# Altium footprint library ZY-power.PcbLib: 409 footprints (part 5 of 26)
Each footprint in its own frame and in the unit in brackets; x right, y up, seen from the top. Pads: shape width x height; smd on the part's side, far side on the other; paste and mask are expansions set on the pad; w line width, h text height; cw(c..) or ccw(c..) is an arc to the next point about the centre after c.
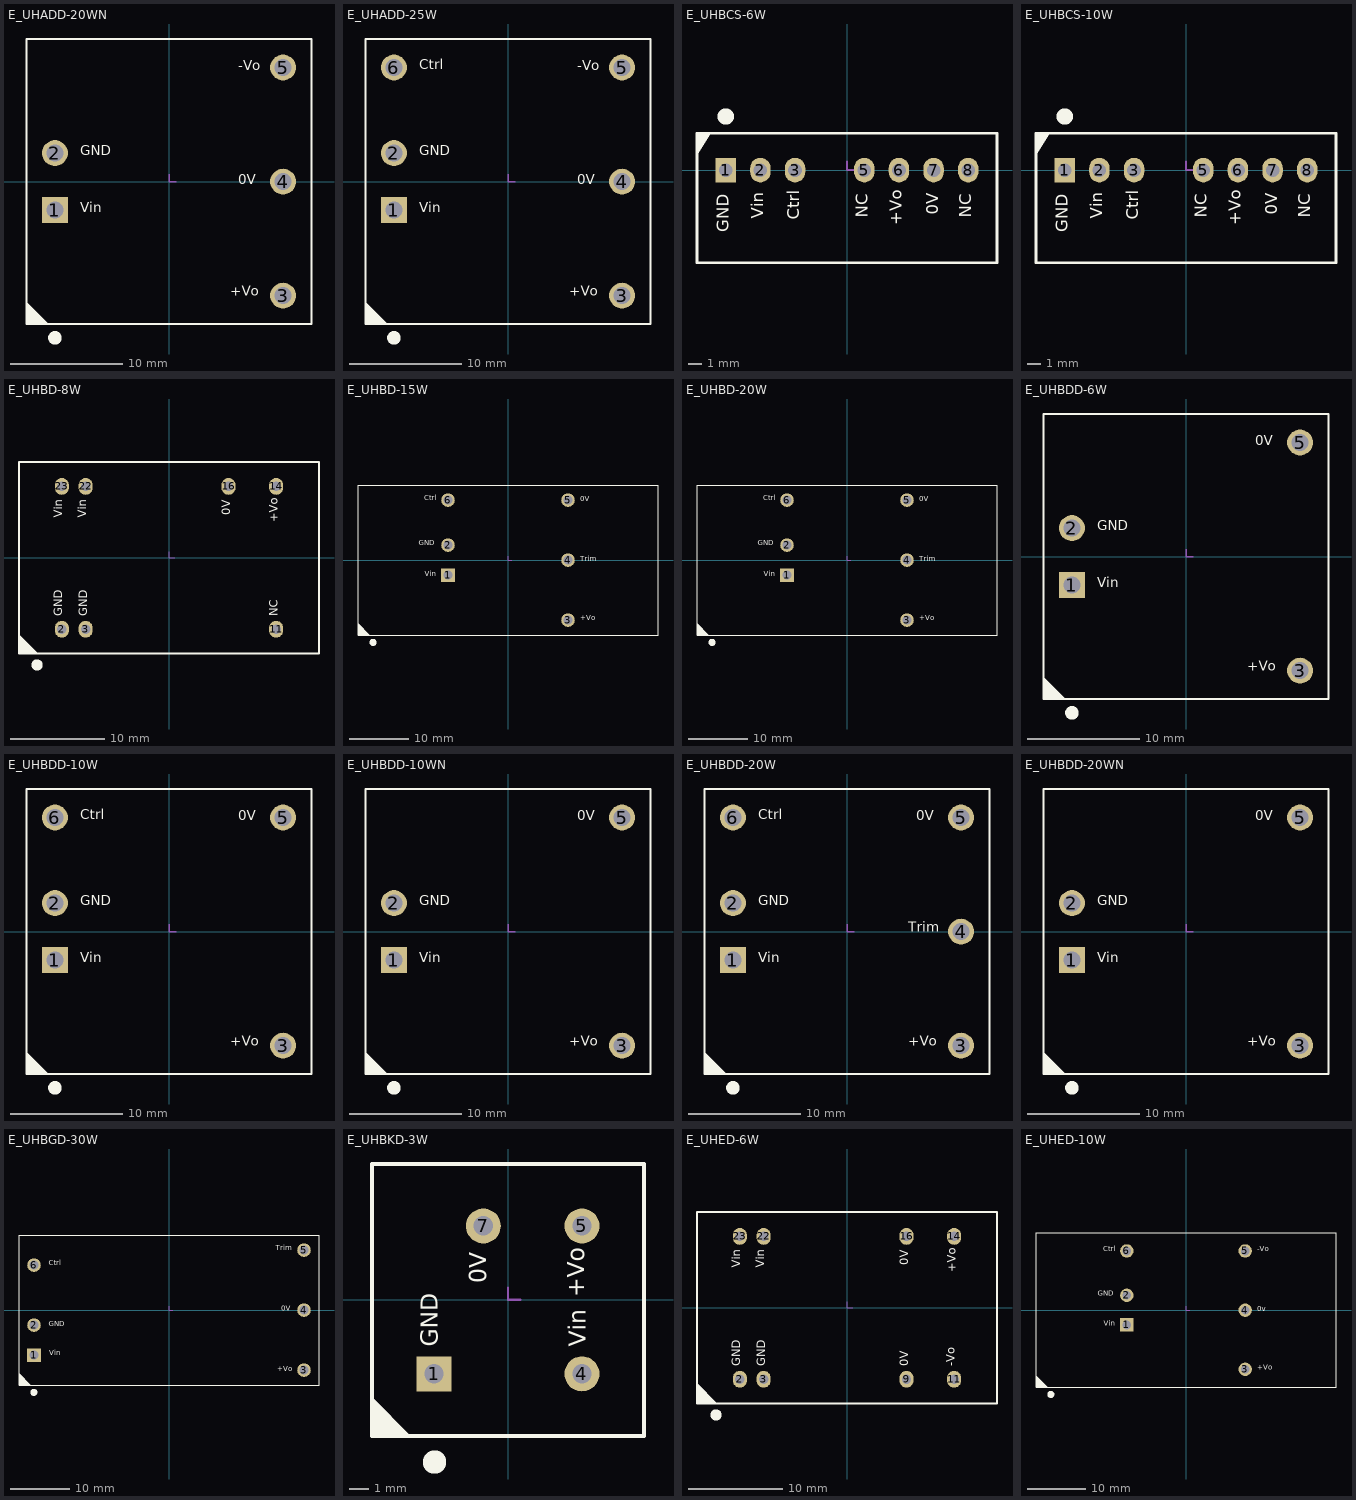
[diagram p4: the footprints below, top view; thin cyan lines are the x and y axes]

## E_UHADD-20WN [mm]
height 11.7
pads (5):
  rect 2.3x2.3 hole 1.5: 1(-10.16,-2.54)
  round 2.3 hole 1.5: 2(-10.16,2.54) 3(10.16,-10.16) 4(10.16,0) 5(10.16,10.16)
Top Overlay:
  circle w1: c-10.16,-13.925 r0.1
  region: -12.7,-12.7 -10.725,-12.7 -12.7,-10.725
  lines w0.2: -12.7,-12.7 12.7,-12.7 12.7,12.7 -12.7,12.7 -12.7,-12.7
  text "-Vo" at 6.175,9.625 h1.52
  text "+Vo" at 5.435,-10.5 h1.52
  text "Vin" at -7.9,-3.025 h1.52
  text "GND" at -7.901,2.05 h1.52
  text "0V" at 6.175,-0.535 h1.52
Mechanical 15:
  lines w0.127: 0,0.635 0,0 0.635,0
3D body: height -1.1, standoff -6.01, extent 9.664,-0.499 10.66,0.499
3D body: height 11.8, standoff 0, extent -12.7,-12.7 12.7,12.7
3D body: height -1.1, standoff -6.01, extent -10.656,2.041 -9.66,3.039
3D body: height -1.1, standoff -6.01, extent -10.656,-3.039 -9.66,-2.041
3D body: height -1.1, standoff -6.01, extent 9.664,-10.659 10.66,-9.661
3D body: height -1.1, standoff -6.01, extent 9.664,9.661 10.66,10.659

## E_UHADD-25W [mm]
height 11.8
pads (6):
  rect 2.3x2.3 hole 1.5: 1(-10.16,-2.54)
  round 2.3 hole 1.5: 2(-10.16,2.54) 3(10.16,-10.16) 4(10.16,0) 5(10.16,10.16) 6(-10.16,10.16)
Top Overlay:
  circle w1: c-10.16,-13.925 r0.1
  region: -12.7,-12.7 -10.725,-12.7 -12.7,-10.725
  lines w0.2: -12.7,-12.7 -12.7,12.7 12.7,12.7 12.7,-12.7 -12.7,-12.7
  text "0V" at 6.175,-0.535 h1.52
  text "GND" at -7.901,2.05 h1.52
  text "Vin" at -7.9,-3.025 h1.52
  text "Ctrl" at -7.901,9.7 h1.52
  text "+Vo" at 5.435,-10.5 h1.52
  text "-Vo" at 6.175,9.625 h1.52
Mechanical 15:
  lines w0.127: 0,0.635 0,0 0.635,0
3D body: height 11.8, standoff 0, extent -12.7,-12.7 12.7,12.7
3D body: height -1.1, standoff -6.01, extent -10.656,2.041 -9.66,3.039
3D body: height -1.1, standoff -6.01, extent -10.656,-3.039 -9.66,-2.041
3D body: height -1.1, standoff -6.01, extent 9.664,-10.659 10.66,-9.661
3D body: height -1.1, standoff -6.01, extent 9.664,9.661 10.66,10.659
3D body: height -1.1, standoff -6.01, extent -10.656,9.661 -9.66,10.659
3D body: height -1.1, standoff -6.01, extent 9.664,-0.499 10.66,0.499

## E_UHBCS-6W [mm]
height 12
pads (7):
  rect 1.5x1.8 hole 1: 1(-8.89,0)
  oval 1.5x1.8 hole 1: 2(-6.35,0) 3(-3.81,0) 5(1.27,0) 6(3.81,0) 7(6.35,0) 8(8.89,0)
Top Overlay:
  circle w1: c-8.89,3.925 r0.1
  region: -11,1.114 -11,2.7 -10.006,2.7
  lines w0.2: -11,-6.8 11,-6.8 11,2.7 -11,2.7 -11,-6.8
  text "NC" at 1.803,-3.502 h1.52
  text "Ctrl" at -3.226,-3.648 h1.52
  text "GND" at -8.382,-4.573 h1.52
  text "Vin" at -5.842,-3.563 h1.52
  text "+Vo" at 4.318,-4.031 h1.52
  text "0V" at 6.985,-3.291 h1.52
  text "NC" at 9.398,-3.502 h1.52
Mechanical 15:
  lines w0.127: 0,0.635 0,0 0.635,0
3D body: height 12, standoff 0, extent -10.93,-6.8 11,2.7
3D body "zhenjao01.stp": height 8.36, standoff -4.08, extent -9.59,-0.12 -8.19,1.48
3D body "zhenjao01.stp": height 8.36, standoff -4.08, extent -7.05,-0.12 -5.65,1.48
3D body "zhenjao01.stp": height 8.36, standoff -4.08, extent -4.51,-0.12 -3.11,1.48
3D body "zhenjao01.stp": height 8.36, standoff -4.08, extent 0.57,-0.12 1.97,1.48
3D body "zhenjao01.stp": height 8.36, standoff -4.08, extent 3.11,-0.12 4.51,1.48
3D body "zhenjao01.stp": height 8.36, standoff -4.08, extent 5.65,-0.12 7.05,1.48
3D body "zhenjao01.stp": height 8.36, standoff -4.08, extent 8.19,-0.12 9.59,1.48

## E_UHBCS-10W [mm]
height 12
pads (7):
  rect 1.5x1.8 hole 1: 1(-8.89,0)
  oval 1.5x1.8 hole 1: 2(-6.35,0) 3(-3.81,0) 5(1.27,0) 6(3.81,0) 7(6.35,0) 8(8.89,0)
Top Overlay:
  circle w1: c-8.89,3.925 r0.1
  region: -11,1.114 -11,2.7 -10.006,2.7
  lines w0.2: -11,-6.8 -11,2.7 11,2.7 11,-6.8 -11,-6.8
  text "NC" at 9.398,-3.502 h1.52
  text "0V" at 6.985,-3.291 h1.52
  text "+Vo" at 4.318,-4.031 h1.52
  text "Vin" at -5.842,-3.563 h1.52
  text "GND" at -8.382,-4.573 h1.52
  text "Ctrl" at -3.226,-3.648 h1.52
  text "NC" at 1.803,-3.502 h1.52
Mechanical 15:
  lines w0.127: 0,0.635 0,0 0.635,0
3D body "zhenjao01.stp": height 8.36, standoff -4.08, extent 8.19,-0.12 9.59,1.48
3D body "zhenjao01.stp": height 8.36, standoff -4.08, extent 5.65,-0.12 7.05,1.48
3D body "zhenjao01.stp": height 8.36, standoff -4.08, extent 3.11,-0.12 4.51,1.48
3D body "zhenjao01.stp": height 8.36, standoff -4.08, extent 0.57,-0.12 1.97,1.48
3D body "zhenjao01.stp": height 8.36, standoff -4.08, extent -4.51,-0.12 -3.11,1.48
3D body "zhenjao01.stp": height 8.36, standoff -4.08, extent -7.05,-0.12 -5.65,1.48
3D body "zhenjao01.stp": height 8.36, standoff -4.08, extent -9.59,-0.12 -8.19,1.48
3D body: height 12, standoff 0, extent -10.93,-6.8 11,2.7

## E_UHBD-8W [mm]
height 11
pads (7):
  oval 1.5x1.8 hole 1: 2(-11.43,-7.62) 3(-8.89,-7.62) 11(11.43,-7.62) 14(11.43,7.62) 16(6.35,7.62) 22(-8.89,7.62) 23(-11.43,7.62)
Top Overlay:
  circle w1: c-14.072,-11.425 r0.1
  region: -16,-10.2 -14.025,-10.2 -16,-8.225
  lines w0.2: -16,-10.2 -16,10.2 16,10.2 16,-10.2 -16,-10.2
  text "GND" at -11.049,-6.223 h1.52
  text "GND" at -8.382,-6.223 h1.52
  text "Vin" at -11.049,4.278 h1.52
  text "Vin" at -8.509,4.278 h1.52
  text "NC" at 11.938,-6.223 h1.52
  text "+Vo" at 11.938,3.81 h1.52
  text "0V" at 6.858,4.55 h1.52
Mechanical 15:
  lines w0.127: 0,0.635 0,0 0.635,0
3D body "zhen01.stp": height 6.09, standoff -4.41, extent -9.14,-7.87 -8.64,-7.37
3D body "zhen01.stp": height 6.09, standoff -4.41, extent -11.68,-7.87 -11.18,-7.37
3D body "zhen01.stp": height 6.09, standoff -4.41, extent 11.18,-7.87 11.68,-7.37
3D body "zhen01.stp": height 6.09, standoff -4.41, extent 11.18,7.37 11.68,7.87
3D body "zhen01.stp": height 6.09, standoff -4.41, extent 6.1,7.37 6.6,7.87
3D body "zhen01.stp": height 6.09, standoff -4.41, extent -9.14,7.37 -8.64,7.87
3D body "zhen01.stp": height 6.09, standoff -4.41, extent -11.68,7.37 -11.18,7.87
3D body: height 11, standoff 0, extent -16,-10.2 16,10.2

## E_UHBD-15W [mm]
height 12.7
pads (6):
  rect 2.3x2.3 hole 1.5: 1(-10.16,-2.54)
  round 2.3 hole 1.5: 2(-10.16,2.54) 3(10.16,-10.16) 4(10.16,0) 5(10.16,10.16) 6(-10.16,10.16)
Top Overlay:
  circle w1: c-22.86,-13.925 r0.1
  region: -25.4,-12.7 -23.425,-12.7 -25.4,-10.725
  lines w0.2: -25.4,-12.7 -25.4,12.7 25.4,12.7 25.4,-12.7 -25.4,-12.7
  text "+Vo" at 12.192,-10.541 h1.52
  text "0V" at 12.192,9.652 h1.52
  text "GND" at -15.113,2.159 h1.52
  text "Vin" at -14.103,-3.048 h1.52
  text "Trim" at 12.192,-0.508 h1.52
  text "Ctrl" at -14.187,9.779 h1.52
Mechanical 15:
  lines w0.127: 0,0.635 0,0 0.635,0
3D body: height 12, standoff 0, extent -25.4,-12.7 25.4,12.7
3D body: height -1.1, standoff -6.01, extent -10.656,2.041 -9.66,3.039
3D body: height -1.1, standoff -6.01, extent -10.656,-3.039 -9.66,-2.041
3D body: height -1.1, standoff -6.01, extent -10.656,9.661 -9.66,10.659
3D body: height -1.1, standoff -6.01, extent 9.664,9.661 10.66,10.659
3D body: height -1.1, standoff -6.01, extent 9.664,-10.659 10.66,-9.661
3D body: height -1.1, standoff -6.01, extent 9.664,-0.499 10.66,0.499

## E_UHBD-20W [mm]
pads (6):
  rect 2.3x2.3 hole 1.5: 1(-10.16,-2.54)
  round 2.3 hole 1.5: 2(-10.16,2.54) 3(10.16,-10.16) 4(10.16,0) 5(10.16,10.16) 6(-10.16,10.16)
Top Overlay:
  circle w1: c-22.86,-13.925 r0.1
  region: -25.4,-12.7 -23.425,-12.7 -25.4,-10.725
  lines w0.2: -25.4,-12.7 -25.4,12.7 25.4,12.7 25.4,-12.7 -25.4,-12.7
  text "Ctrl" at -14.187,9.779 h1.52
  text "Trim" at 12.192,-0.508 h1.52
  text "Vin" at -14.103,-3.048 h1.52
  text "GND" at -15.113,2.159 h1.52
  text "0V" at 12.192,9.652 h1.52
  text "+Vo" at 12.192,-10.541 h1.52
Mechanical 15:
  lines w0.127: 0,0.635 0,0 0.635,0
3D body: height 12, standoff 0, extent -25.4,-12.7 25.4,12.7
3D body: height -1.1, standoff -6.01, extent -10.656,2.041 -9.66,3.039
3D body: height -1.1, standoff -6.01, extent -10.656,-3.039 -9.66,-2.041
3D body: height -1.1, standoff -6.01, extent -10.656,9.661 -9.66,10.659
3D body: height -1.1, standoff -6.01, extent 9.664,9.661 10.66,10.659
3D body: height -1.1, standoff -6.01, extent 9.664,-10.659 10.66,-9.661
3D body: height -1.1, standoff -6.01, extent 9.664,-0.499 10.66,0.499

## E_UHBDD-6W [mm]
height 11.7
pads (4):
  rect 2.3x2.3 hole 1.5: 1(-10.16,-2.54)
  round 2.3 hole 1.5: 2(-10.16,2.54) 3(10.16,-10.16) 5(10.16,10.16)
Top Overlay:
  circle w1: c-10.16,-13.925 r0.1
  region: -12.7,-12.7 -10.725,-12.7 -12.7,-10.725
  lines w0.2: -12.7,-12.7 12.7,-12.7 12.7,12.7 -12.7,12.7 -12.7,-12.7
  text "0V" at 6.175,9.625 h1.52
  text "+Vo" at 5.435,-10.5 h1.52
  text "Vin" at -7.9,-3.025 h1.52
  text "GND" at -7.901,2.05 h1.52
Mechanical 15:
  lines w0.127: 0,0.635 0,0 0.635,0
3D body: height -1.1, standoff -6.01, extent 9.664,9.661 10.66,10.659
3D body: height -1.1, standoff -6.01, extent 9.664,-10.659 10.66,-9.661
3D body: height -1.1, standoff -6.01, extent -10.656,-3.039 -9.66,-2.041
3D body: height -1.1, standoff -6.01, extent -10.656,2.041 -9.66,3.039
3D body: height 11.8, standoff 0, extent -12.7,-12.7 12.7,12.7

## E_UHBDD-10W [mm]
height 11.8
pads (5):
  rect 2.3x2.3 hole 1.5: 1(-10.16,-2.54)
  round 2.3 hole 1.5: 2(-10.16,2.54) 3(10.16,-10.16) 5(10.16,10.16) 6(-10.16,10.16)
Top Overlay:
  circle w1: c-10.16,-13.925 r0.1
  region: -12.7,-12.7 -10.725,-12.7 -12.7,-10.725
  lines w0.2: -12.7,-12.7 12.7,-12.7 12.7,12.7 -12.7,12.7 -12.7,-12.7
  text "0V" at 6.175,9.625 h1.52
  text "+Vo" at 5.435,-10.5 h1.52
  text "Ctrl" at -7.901,9.7 h1.52
  text "Vin" at -7.9,-3.025 h1.52
  text "GND" at -7.901,2.05 h1.52
Mechanical 15:
  lines w0.127: 0,0.635 0,0 0.635,0
3D body: height 11.8, standoff 0, extent -12.7,-12.7 12.7,12.7
3D body: height -1.1, standoff -6.01, extent -10.656,2.041 -9.66,3.039
3D body: height -1.1, standoff -6.01, extent -10.656,-3.039 -9.66,-2.041
3D body: height -1.1, standoff -6.01, extent 9.664,-10.659 10.66,-9.661
3D body: height -1.1, standoff -6.01, extent 9.664,9.661 10.66,10.659
3D body: height -1.1, standoff -6.01, extent -10.656,9.661 -9.66,10.659

## E_UHBDD-10WN [mm]
height 11.8
pads (4):
  rect 2.3x2.3 hole 1.5: 1(-10.16,-2.54)
  round 2.3 hole 1.5: 2(-10.16,2.54) 3(10.16,-10.16) 5(10.16,10.16)
Top Overlay:
  circle w1: c-10.16,-13.925 r0.1
  region: -12.7,-12.7 -10.725,-12.7 -12.7,-10.725
  lines w0.2: -12.7,-12.7 -12.7,12.7 12.7,12.7 12.7,-12.7 -12.7,-12.7
  text "GND" at -7.901,2.05 h1.52
  text "Vin" at -7.9,-3.025 h1.52
  text "+Vo" at 5.435,-10.5 h1.52
  text "0V" at 6.175,9.625 h1.52
Mechanical 15:
  lines w0.127: 0,0.635 0,0 0.635,0
3D body: height 11.8, standoff 0, extent -12.7,-12.7 12.7,12.7
3D body: height -1.1, standoff -6.01, extent -10.656,2.041 -9.66,3.039
3D body: height -1.1, standoff -6.01, extent -10.656,-3.039 -9.66,-2.041
3D body: height -1.1, standoff -6.01, extent 9.664,-10.659 10.66,-9.661
3D body: height -1.1, standoff -6.01, extent 9.664,9.661 10.66,10.659

## E_UHBDD-20W [mm]
height 11.8
pads (6):
  rect 2.3x2.3 hole 1.5: 1(-10.16,-2.54)
  round 2.3 hole 1.5: 2(-10.16,2.54) 3(10.16,-10.16) 4(10.16,0) 5(10.16,10.16) 6(-10.16,10.16)
Top Overlay:
  circle w1: c-10.16,-13.925 r0.1
  region: -12.7,-12.7 -10.725,-12.7 -12.7,-10.725
  lines w0.2: -12.7,-12.7 -12.7,12.7 12.7,12.7 12.7,-12.7 -12.7,-12.7
  text "GND" at -7.901,2.05 h1.52
  text "Vin" at -7.9,-3.025 h1.52
  text "Ctrl" at -7.901,9.7 h1.52
  text "+Vo" at 5.435,-10.5 h1.52
  text "0V" at 6.175,9.625 h1.52
  text "Trim" at 5.435,-0.34 h1.52
Mechanical 15:
  lines w0.127: 0,0.635 0,0 0.635,0
3D body "25.40×25.40×11.80（1、2、3、4、5、6脚）.stp": height 11.8, standoff -5.2, extent -12.7,-12.7 12.7,12.7

## E_UHBDD-20WN [mm]
height 11.8
pads (4):
  rect 2.3x2.3 hole 1.5: 1(-10.16,-2.54)
  round 2.3 hole 1.5: 2(-10.16,2.54) 3(10.16,-10.16) 5(10.16,10.16)
Top Overlay:
  circle w1: c-10.16,-13.925 r0.1
  region: -12.7,-12.7 -10.725,-12.7 -12.7,-10.725
  lines w0.2: -12.7,-12.7 12.7,-12.7 12.7,12.7 -12.7,12.7 -12.7,-12.7
  text "0V" at 6.175,9.625 h1.52
  text "+Vo" at 5.435,-10.5 h1.52
  text "Vin" at -7.9,-3.025 h1.52
  text "GND" at -7.901,2.05 h1.52
Mechanical 15:
  lines w0.127: 0,0.635 0,0 0.635,0
3D body: height -1.1, standoff -6.01, extent 9.664,9.661 10.66,10.659
3D body: height -1.1, standoff -6.01, extent 9.664,-10.659 10.66,-9.661
3D body: height -1.1, standoff -6.01, extent -10.656,-3.039 -9.66,-2.041
3D body: height -1.1, standoff -6.01, extent -10.656,2.041 -9.66,3.039
3D body: height 11.8, standoff 0, extent -12.7,-12.7 12.7,12.7

## E_UHBGD-30W [mm]
height 12.7
pads (6):
  rect 2.3x2.3 hole 1.5: 1(-22.86,-7.62)
  round 2.3 hole 1.5: 2(-22.86,-2.54) 3(22.86,-10.16) 4(22.86,0) 5(22.86,10.16) 6(-22.86,7.62)
Top Overlay:
  circle w1: c-22.887,-13.925 r0.1
  region: -25.4,-12.7 -23.425,-12.7 -25.4,-10.725
  lines w0.2: -25.4,-12.7 25.4,-12.7 25.4,12.7 -25.4,12.7 -25.4,-12.7
  text "Ctrl" at -20.321,7.239 h1.52
  text "Trim" at 18.034,9.779 h1.52
  text "Vin" at -20.32,-8.001 h1.52
  text "GND" at -20.321,-3.048 h1.52
  text "0V" at 19.041,-0.445 h1.52
  text "+Vo" at 18.301,-10.668 h1.52
Mechanical 15:
  lines w0.127: 0,0.635 0,0 0.635,0
3D body: height -1.1, standoff -6.01, extent -23.356,7.121 -22.36,8.119
3D body: height 12.7, standoff 0, extent -25.4,-12.7 25.4,12.7
3D body: height -1.1, standoff -6.01, extent -23.356,-3.039 -22.36,-2.041
3D body: height -1.1, standoff -6.01, extent -23.356,-8.119 -22.36,-7.121
3D body: height -1.1, standoff -6.01, extent 22.364,-10.659 23.36,-9.661
3D body: height -1.1, standoff -6.01, extent 22.364,-0.499 23.36,0.499
3D body: height -1.1, standoff -6.01, extent 22.364,9.661 23.36,10.659

## E_UHBKD-3W [mm]
height 10
pads (4):
  rect 1.8x1.8 hole 1: 1(-3.81,-3.81)
  round 1.8 hole 1: 4(3.81,-3.81) 5(3.81,3.81) 7(-1.27,3.81)
Top Overlay:
  circle w1: c-3.783,-8.35 r0.1
  region: -7,-7 -5.025,-7 -7,-5.025
  lines w0.2: -7,-7 -7,7 7,7 7,-7 -7,-7
  text "0V" at -0.813,0.864 h1.52
  text "+Vo" at 4.244,0.127 h1.52
  text "Vin" at 4.318,-2.413 h1.52
  text "GND" at -3.302,-2.413 h1.52
Mechanical 15:
  lines w0.127: 0,0.635 0,0 0.635,0
3D body: height 10, standoff 0, extent -7,-7 7,7
3D body "zhen01.stp": height 6.09, standoff -4.41, extent -4.06,-4.06 -3.56,-3.56
3D body "zhen01.stp": height 6.09, standoff -4.41, extent 3.56,-4.06 4.06,-3.56
3D body "zhen01.stp": height 6.09, standoff -4.41, extent -1.52,3.56 -1.02,4.06
3D body "zhen01.stp": height 6.09, standoff -4.41, extent 3.56,3.56 4.06,4.06

## E_UHED-6W [mm]
height 11
pads (8):
  oval 1.5x1.8 hole 1: 2(-11.43,-7.62) 3(-8.89,-7.62) 9(6.35,-7.62) 11(11.43,-7.62) 14(11.43,7.62) 16(6.35,7.62) 22(-8.89,7.62) 23(-11.43,7.62)
Top Overlay:
  circle w1: c-13.97,-11.425 r0.1
  region: -15.898,-10.103 -13.923,-10.103 -15.898,-8.128
  lines w0.2: -16,-10.2 16,-10.2 16,10.2 -16,10.2 -16,-10.2
  text "0V" at 6.833,-6.223 h1.52
  text "0V" at 6.858,4.55 h1.52
  text "+Vo" at 11.938,3.81 h1.52
  text "-Vo" at 11.811,-6.223 h1.52
  text "Vin" at -8.509,4.278 h1.52
  text "Vin" at -11.049,4.278 h1.52
  text "GND" at -8.382,-6.223 h1.52
  text "GND" at -11.049,-6.223 h1.52
Mechanical 15:
  lines w0.127: 0,0.635 0,0 0.635,0
3D body "zhen01.stp": height 6.09, standoff -4.41, extent 6.1,-7.87 6.6,-7.37
3D body: height 11, standoff 0, extent -16,-10.2 16,10.2
3D body "zhen01.stp": height 6.09, standoff -4.41, extent -11.68,7.37 -11.18,7.87
3D body "zhen01.stp": height 6.09, standoff -4.41, extent -9.14,7.37 -8.64,7.87
3D body "zhen01.stp": height 6.09, standoff -4.41, extent 6.1,7.37 6.6,7.87
3D body "zhen01.stp": height 6.09, standoff -4.41, extent 11.18,7.37 11.68,7.87
3D body "zhen01.stp": height 6.09, standoff -4.41, extent 11.18,-7.87 11.68,-7.37
3D body "zhen01.stp": height 6.09, standoff -4.41, extent -11.68,-7.87 -11.18,-7.37
3D body "zhen01.stp": height 6.09, standoff -4.41, extent -9.14,-7.87 -8.64,-7.37

## E_UHED-10W [mm]
height 12
pads (6):
  rect 2.3x2.3 hole 1.5: 1(-10.16,-2.54)
  round 2.3 hole 1.5: 2(-10.16,2.54) 3(10.16,-10.16) 4(10.16,0) 5(10.16,10.16) 6(-10.16,10.16)
Top Overlay:
  circle w1: c-23.21,-14.475 r0.1
  region: -25.75,-13.25 -23.775,-13.25 -25.75,-11.275
  lines w0.2: -25.75,-13.25 25.75,-13.25 25.75,13.25 -25.75,13.25 -25.75,-13.25
  text "Ctrl" at -14.187,9.779 h1.52
  text "0v" at 12.192,-0.508 h1.52
  text "Vin" at -14.103,-3.048 h1.52
  text "GND" at -15.113,2.159 h1.52
  text "-Vo" at 12.192,9.796 h1.52
  text "+Vo" at 12.192,-10.541 h1.52
Mechanical 15:
  lines w0.127: 0,0.635 0,0 0.635,0
3D body: height 12, standoff 0, extent -25.75,-13.25 25.75,13.25
3D body: height -1.1, standoff -6.01, extent -10.656,2.041 -9.66,3.039
3D body: height -1.1, standoff -6.01, extent -10.656,-3.039 -9.66,-2.041
3D body: height -1.1, standoff -6.01, extent -10.656,9.661 -9.66,10.659
3D body: height -1.1, standoff -6.01, extent 9.664,9.661 10.66,10.659
3D body: height -1.1, standoff -6.01, extent 9.664,-10.659 10.66,-9.661
3D body: height -1.1, standoff -6.01, extent 9.664,-0.499 10.66,0.499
